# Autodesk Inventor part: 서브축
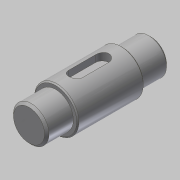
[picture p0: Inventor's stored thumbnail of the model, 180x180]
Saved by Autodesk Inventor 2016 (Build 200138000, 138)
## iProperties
Created: 2019-03
Part Number: 서브축
Material: 강철, 연강
Document SubType Name: Modeling
Designer: mduedu
Density: 1 g/cm^3
Appearance: 강철
Author: mduedu
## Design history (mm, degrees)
sketch "스케치1"
  geometry: L1 (0, 0)-(12, 0); L2 (12, 0)-(12, 8); L3 (12, 8)-(0, 8); L4 (0, 8)-(0, 0); L5 (12, 0)-(42, 0); L6 (42, 0)-(42, 10); L7 (42, 10)-(12, 10); L8 (12, 10)-(12, 0); L9 (42, 0)-(55, 0); L10 (55, 0)-(55, 8); L11 (55, 8)-(42, 8); L12 (42, 8)-(42, 0)
  constraints: 24 end point, 6 parallel, 3 horizontal, 3 perpendicular
  dimensions: "d0" = 16 diameter of L3 L1; "d2" = 20 diameter of L7 L5; "d3" = 16 diameter of L11 L9; "d4" = 12 distance of L2.end L3.end; "d5" = 30 distance of L6.end L7.end; "d6" = 55 distance between parallel lines of L10 L4
revolve "회전1" sketch "스케치1" stored, may be unused: angle "d7" = 90 deg
node "작업 평면1"
sketch "스케치2" dims "d10" = 18
  geometry: L1 (6, -3)-(-6, -3); L2 (-6, -3)-(-6, 3); L3 (-6, 3)-(6, 3); L4 (6, 3)-(6, -3); L5 (15, 10)-(15, -10) reference; 3 further points
  constraints: 8 end point, 2 midpoint, 2 parallel, 2 vertical alignment, 1 horizontal, 1 horizontal alignment, 1 perpendicular, 4 other
  dimensions: "d8" = 6 distance between parallel lines of L3 L1; "d11" = 6 dimension on L5
extrude "돌출1" cut sketch "스케치2" distance "d12" = 3.5; taper "d13" = 0 deg
chamfer "모따기1" distance "d14" = 1; stored, may be unused: second distance "d15" = 2, angle "d16" = 45 deg
chamfer "모따기2" distance "d17" = 0.5; stored, may be unused: second distance "d18" = 2, angle "d19" = 45 deg
node "솔리드1"
